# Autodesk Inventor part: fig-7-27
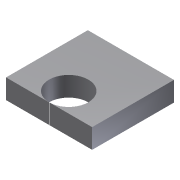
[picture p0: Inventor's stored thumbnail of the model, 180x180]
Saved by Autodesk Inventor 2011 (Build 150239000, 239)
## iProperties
Created: 2005-04
Part Number: fig-7-27
Document SubType Name: Modeling
Designer: CADCIM
Density: 1 g/cm^3
Author: CADCIM
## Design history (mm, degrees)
sketch "Sketch1"
  geometry: L1 (9.851, -16.047)-(9.851, -1.297); L2 (9.851, -1.297)-(-12.082, -1.297); L3 (-12.082, -1.297)-(-12.082, -16.047); L4 (-12.082, -16.047)-(9.851, -16.047)
  constraints: 8 end point, 2 parallel, 1 perpendicular, 1 vertical
extrude "Extrusion1" new body sketch "Sketch1" distance "d0" = 5; taper "d1" = 0 deg
sketch "Sketch2"
  geometry: C1 r 5 at (-1.115, -17.135); 1 further point
  constraints: 1 centre point
  dimensions: "d7" = 10.96654 horizontal distance of point (-12.082, -16.047) C1.centre; "d8" = 10 diameter of C1
extrude "Extrusion2" cut sketch "Sketch2" stored distance "d2" = 5; taper "d3" = 0 deg
feature "Move Face3" dims "d9" = 6.088
body "Solid1"
